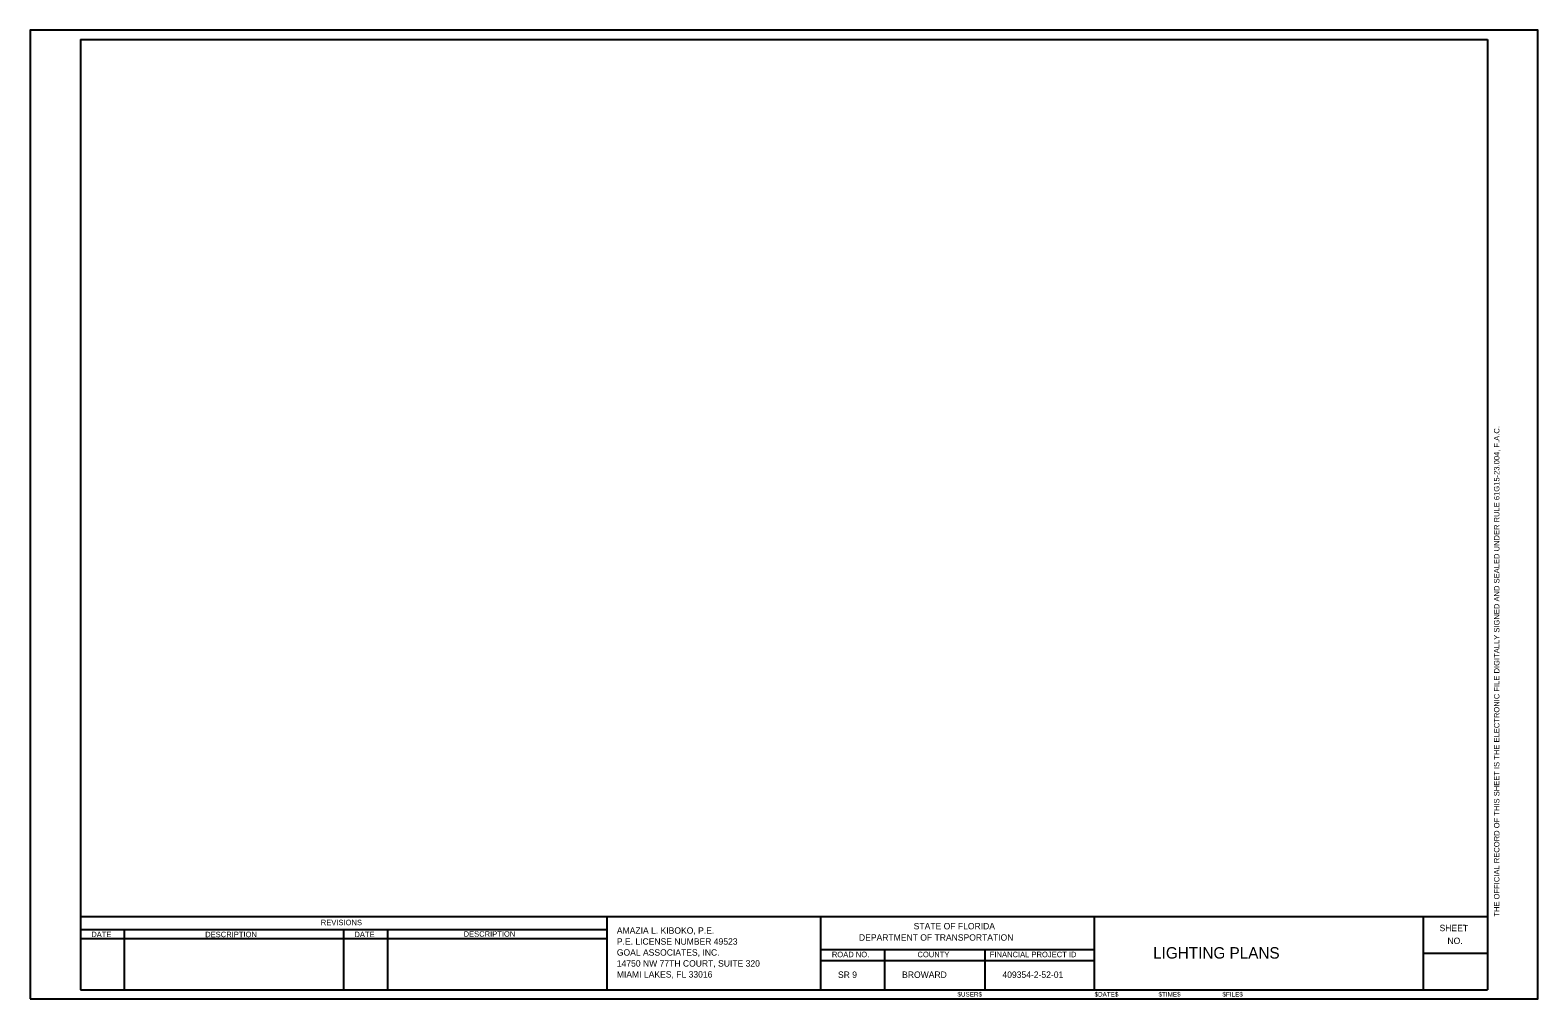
# Model space of a CAD drawing. Extents: x -816.7 to -800.2, y -2197.9 to -2187.3.
import ezdxf

# ---------------------------------------------------------------- set-up
doc = ezdxf.new("R2010")
doc.units = 0
for name, color, linetype in [('AdhocPoint_dp', 7, 'Continuous'), ('PlotBorder_dp', 7, 'Continuous'), ('SheetBorder_dp', 7, 'Continuous'), ('SheetLines_dp', 7, 'Continuous'), ('TextLabel', 7, 'Continuous'), ('TextMinor', 7, 'Continuous'), ('TextMisc', 7, 'Continuous'), ('TextTitle', 7, 'Continuous')]:
    doc.layers.add(name, color=color, linetype=linetype)

msp = doc.modelspace()

# ---------------------------------------------------------------- linework, layer by layer
at = {"layer": 'AdhocPoint_dp'}
msp.add_line((-816.669, -2197.899), (-816.669, -2197.899), dxfattribs=at)
msp.add_line((-816.669, -2197.899), (-816.669, -2197.899), dxfattribs=at)
at = {"layer": 'PlotBorder_dp'}
msp.add_lwpolyline([(-816.669, -2197.899), (-800.169, -2197.899), (-800.169, -2187.299), (-816.669, -2187.299)], close=True, dxfattribs=at)
at = {"layer": 'SheetBorder_dp'}
for p, q in [((-816.119, -2187.399), (-816.119, -2197.799)), ((-816.119, -2187.399), (-800.719, -2187.399)), ((-800.719, -2187.399), (-800.719, -2197.799)), ((-816.119, -2196.999), (-800.719, -2196.999)), ((-816.119, -2197.799), (-800.719, -2197.799))]:
    msp.add_line(p, q, dxfattribs=at)
at = {"layer": 'SheetLines_dp'}
for p, q in [((-816.119, -2197.139), (-810.359, -2197.139)), ((-815.639, -2197.139), (-815.639, -2197.799)), ((-813.239, -2197.139), (-813.239, -2197.799)), ((-812.759, -2197.139), (-812.759, -2197.799)), ((-810.359, -2196.999), (-810.359, -2197.799)), ((-808.019, -2196.999), (-808.019, -2197.799)), ((-805.019, -2197.799), (-805.019, -2196.999)), ((-801.419, -2197.799), (-801.419, -2196.999)), ((-816.119, -2197.239), (-810.359, -2197.239)), ((-808.019, -2197.359), (-805.019, -2197.359)), ((-807.319, -2197.359), (-807.319, -2197.799)), ((-806.219, -2197.359), (-806.219, -2197.799)), ((-801.419, -2197.399), (-800.719, -2197.399)), ((-808.019, -2197.479), (-805.019, -2197.479))]:
    msp.add_line(p, q, dxfattribs=at)

# ---------------------------------------------------------------- texts
at = {"layer": 'TextLabel'}
msp.add_text('        LIGHTING PLANS         ', height=0.125, dxfattribs=at).set_placement((-804.75, -2197.458))
at = {"layer": 'TextMinor'}
msp.add_text('$USER$', height=0.05, dxfattribs=at).set_placement((-806.52, -2197.874))
for s, p in [('$DATE$', (-805.02, -2197.874)), ('$TIME$', (-804.32, -2197.874)), ('$FILE$', (-803.62, -2197.874))]:
    msp.add_text(s, height=0.05, rotation=360, dxfattribs=at).set_placement(p)
at = {"layer": 'TextMisc'}
for s, height, rotation, p in [('THE OFFICIAL RECORD OF THIS SHEET IS THE ELECTRONIC FILE DIGITALLY SIGNED AND SEALED UNDER RULE 61G15-23.004, F.A.C.', 0.06, 90, (-800.589, -2196.999)), ('SHEET', 0.07, 359.8607, (-801.244, -2197.158)), ('DATE', 0.06, 359.8693, (-816, -2197.223)), ('DESCRIPTION', 0.06, 0.0498, (-814.753, -2197.224)), ('DATE', 0.06, 359.8693, (-813.12, -2197.223)), ('DESCRIPTION', 0.06, 0.0498, (-811.925, -2197.219)), ('NO.', 0.07, 359.8607, (-801.158, -2197.298))]:
    msp.add_text(s, height=height, rotation=rotation, dxfattribs=at).set_placement(p)
for s, height, p in [('REVISIONS', 0.06, (-813.488, -2197.093)), ('STATE OF FLORIDA', 0.07, (-806.999, -2197.138)), ('DEPARTMENT OF TRANSPORTATION', 0.07, (-807.598, -2197.262)), ('ROAD NO.', 0.06, (-807.895, -2197.443)), ('COUNTY', 0.06, (-806.958, -2197.443)), ('FINANCIAL PROJECT ID', 0.06, (-806.166, -2197.443)), (' SR 9  ', 0.07, (-807.854, -2197.669)), ('  BROWARD   ', 0.07, (-807.178, -2197.669)), ('409354-2-52-01', 0.07, (-806.028, -2197.669))]:
    msp.add_text(s, height=height, dxfattribs=at).set_placement(p)
at = {"layer": 'TextTitle'}
for s, p in [('AMAZIA L. KIBOKO, P.E.', (-810.248, -2197.186)), ('P.E. LICENSE NUMBER 49523', (-810.248, -2197.306)), ('GOAL ASSOCIATES, INC.', (-810.248, -2197.426)), ('14750 NW 77TH COURT, SUITE 320', (-810.248, -2197.546)), ('MIAMI LAKES, FL 33016', (-810.248, -2197.666))]:
    msp.add_text(s, height=0.07, dxfattribs=at).set_placement(p)

doc.saveas('drawing.dxf')
